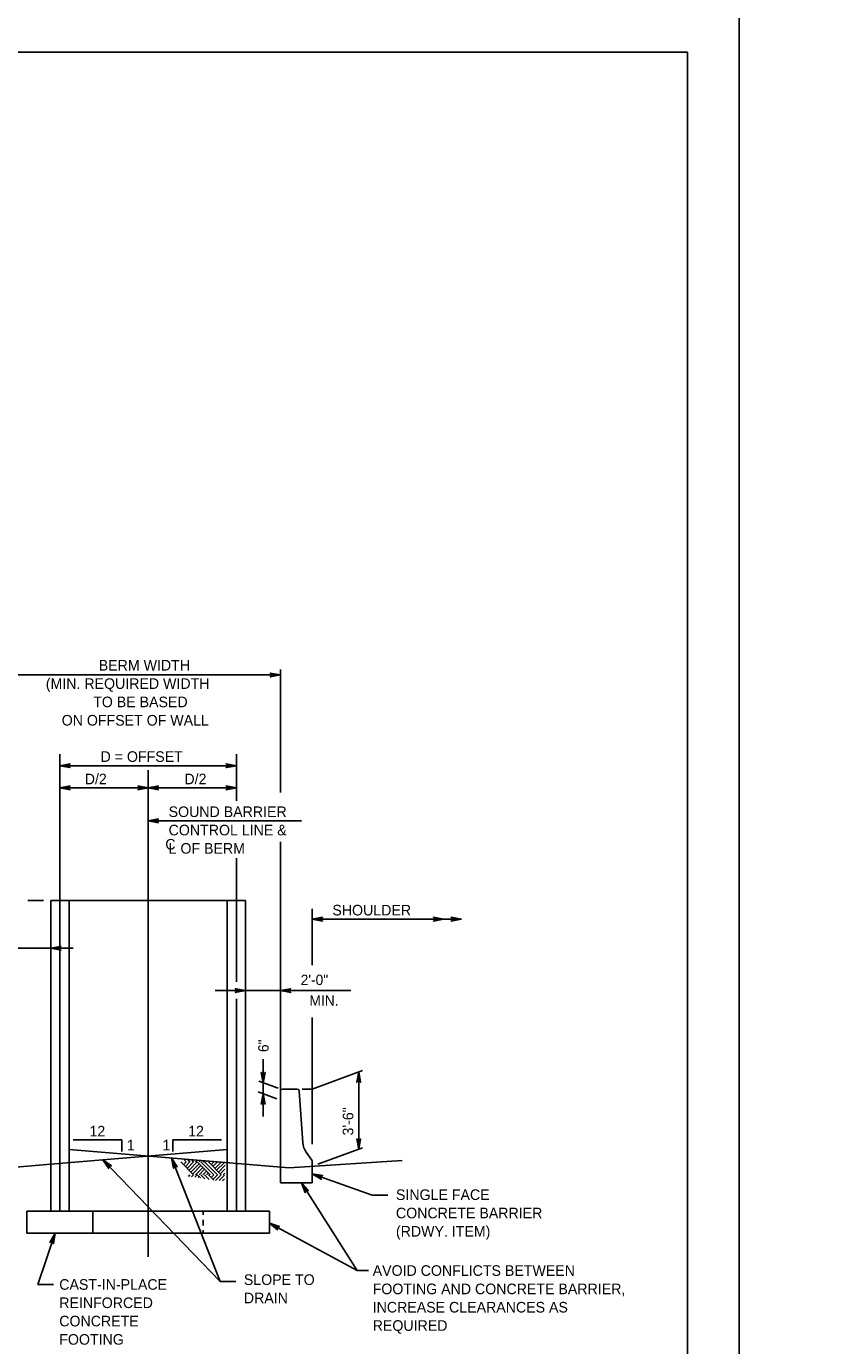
# Model space of a CAD drawing. Extents: x 3385 to 6532, y -616 to 1166.
# Drawn here: x 4395.6 to 4629.5, y 181.7 to 564.2 of the extents above; entities that cross this region are included whole.
import ezdxf

# ---------------------------------------------------------------- set-up
doc = ezdxf.new("R2010")
doc.units = 0
for name, color, linetype in [('1', 7, 'Continuous'), ('2', 7, 'Continuous'), ('PLT-BNDY', 7, 'Continuous')]:
    doc.layers.add(name, color=color, linetype=linetype)

msp = doc.modelspace()

# ---------------------------------------------------------------- linework, layer by layer
at = {"layer": '1'}
for p, q in [((4392.54, 376.13), (4469.34, 376.13)), ((4469.34, 377.67), (4469.34, 342.04)), ((4405.34, 353.19), (4405.34, 220.62)), ((4456.54, 353.19), (4456.54, 339.58)), ((4405.34, 349.81), (4456.54, 349.81)), ((4430.94, 348.49), (4430.94, 207.41)), ((4405.34, 343.41), (4456.54, 343.41)), ((4430.94, 333.81), (4475.42, 333.81)), ((4469.34, 327.78), (4469.34, 253.06)), ((4456.54, 323.03), (4456.54, 287.16)), ((4396.01, 310.76), (4400.62, 310.76)), ((4402.68, 310.76), (4402.68, 220.62)), ((4402.68, 310.76), (4459.21, 310.76)), ((4408.01, 310.76), (4408.01, 220.62)), ((4453.88, 310.76), (4453.88, 220.62)), ((4459.21, 310.76), (4459.21, 220.62)), ((4478.55, 308.31), (4478.55, 291.94)), ((4478.55, 305.32), (4521.77, 305.32)), ((4373.95, 296.86), (4409.23, 296.86)), ((4450.39, 284.59), (4489.76, 284.59)), ((4456.54, 282.2), (4456.54, 220.62)), ((4478.55, 276.76), (4478.55, 240.11)), ((4464.31, 264.69), (4464.31, 248.13)), ((4478.55, 256.04), (4493.11, 261.41)), ((4492.02, 261.01), (4492.02, 238.61)), ((4468.63, 256.31), (4463.09, 258.35)), ((4468.27, 253.24), (4462.81, 255.25)), ((4469.34, 255.51), (4469.34, 228.84)), ((4469.88, 256.04), (4474.18, 256.04)), ((4474.71, 255.55), (4475.77, 240.48)), ((4475.65, 256.04), (4478.55, 256.04)), ((4409.21, 241.35), (4423.31, 241.35)), ((4423.31, 241.35), (4423.31, 237.93)), ((4452.19, 241.35), (4438.09, 241.35)), ((4438.09, 241.35), (4438.09, 237.93)), ((4402.68, 234.27), (4453.88, 238.54)), ((4471.83, 233.22), (4408.01, 238.54)), ((4476.75, 237.75), (4478.45, 235.38)), ((4480.13, 234.23), (4493.15, 239.02)), ((4392.54, 233.42), (4402.68, 234.27)), ((4451.8, 200.27), (4417.85, 235.53)), ((4451.8, 200.27), (4437.74, 236.06)), ((4444.14, 231.19), (4440.41, 234.92)), ((4442.01, 234.92), (4441.16, 235.77)), ((4441.21, 234.12), (4442.01, 234.92)), ((4441.74, 233.59), (4443.07, 234.92)), ((4442.27, 233.05), (4444.14, 234.92)), ((4443.07, 234.92), (4442.32, 235.68)), ((4442.81, 232.52), (4445.21, 234.92)), ((4443.34, 231.99), (4445.74, 234.39)), ((4444.14, 234.92), (4443.48, 235.58)), ((4443.87, 235.19), (4444.21, 235.52)), ((4443.87, 231.45), (4446.27, 233.85)), ((4444.67, 234.92), (4445.19, 235.44)), ((4448.94, 231.19), (4445.21, 234.92)), ((4445.74, 234.92), (4446.18, 235.36)), ((4450.01, 231.19), (4446.27, 234.92)), ((4446.81, 234.92), (4447.16, 235.27)), ((4451.08, 231.19), (4447.34, 234.92)), ((4447.88, 234.92), (4448.15, 235.19)), ((4452.14, 231.19), (4448.41, 234.92)), ((4448.94, 234.92), (4448.72, 235.14)), ((4449.21, 234.12), (4450.01, 234.92)), ((4449.74, 233.59), (4451.08, 234.92)), ((4450.01, 234.92), (4449.88, 235.05)), ((4450.28, 233.05), (4452.08, 234.86)), ((4450.81, 232.52), (4453.07, 234.78)), ((4451.08, 234.92), (4451.05, 234.95)), ((4451.34, 231.99), (4453.21, 233.85)), ((4453.21, 233.85), (4453.26, 233.91)), ((4471.83, 233.22), (4504.63, 235.29)), ((4478.55, 235.07), (4478.55, 228.84)), ((4442.61, 230.72), (4443.07, 231.19)), ((4443.56, 230.6), (4444.14, 231.19)), ((4444.5, 230.48), (4445.21, 231.19)), ((4444.67, 231.19), (4446.81, 233.32)), ((4446.12, 230.28), (4445.21, 231.19)), ((4445.45, 230.36), (4445.74, 230.65)), ((4445.74, 231.19), (4447.34, 232.79)), ((4447.4, 230.06), (4446.27, 231.19)), ((4446.81, 231.19), (4447.88, 232.25)), ((4448.69, 229.84), (4447.34, 231.19)), ((4447.88, 231.19), (4448.41, 231.72)), ((4449.98, 229.62), (4448.41, 231.19)), ((4449.21, 230.39), (4450.01, 231.19)), ((4449.74, 229.85), (4451.08, 231.19)), ((4450.5, 229.54), (4452.14, 231.19)), ((4451.51, 229.49), (4453.12, 231.1)), ((4451.88, 231.45), (4453.21, 232.78)), ((4452.52, 229.44), (4453.06, 229.98)), ((4452.68, 231.19), (4453.15, 231.66)), ((4478.55, 231.43), (4495.91, 225.31)), ((4469.34, 228.84), (4478.55, 228.84)), ((4495.91, 225.31), (4500.46, 225.31)), ((4395.74, 220.62), (4466.14, 220.62)), ((4395.74, 220.62), (4395.74, 214.22)), ((4414.94, 220.62), (4414.94, 214.22)), ((4446.94, 220.62), (4446.94, 219.58)), ((4446.94, 218.11), (4446.94, 216.47)), ((4466.14, 220.62), (4466.14, 214.22)), ((4395.74, 214.22), (4466.14, 214.22)), ((4398.95, 199.36), (4403.97, 214.22)), ((4446.94, 215.09), (4446.94, 214.22)), ((4398.95, 199.36), (4403.49, 199.36)), ((4451.8, 200.27), (4456.34, 200.27))]:
    msp.add_line(p, q, dxfattribs=at)
for points in [[(4469.34, 376.13), (4466.36, 375.57), (4466.59, 375.73), (4466.71, 375.93), (4466.74, 376.13), (4466.71, 376.33), (4466.59, 376.53), (4466.36, 376.69), (4469.34, 376.13), (4466.59, 376.53), (4466.71, 376.33), (4469.34, 376.13), (4466.74, 376.13), (4466.71, 375.93), (4469.34, 376.13), (4466.59, 375.73)], [(4405.34, 349.81), (4408.33, 350.37), (4408.21, 350.29), (4408.1, 350.21), (4408.04, 350.11), (4407.98, 350.01), (4407.96, 349.91), (4407.94, 349.81), (4407.96, 349.71), (4407.98, 349.61), (4408.04, 349.51), (4408.1, 349.41), (4408.21, 349.33), (4408.33, 349.25), (4405.34, 349.81), (4408.21, 349.33), (4408.1, 349.41), (4405.34, 349.81), (4408.04, 349.51), (4407.98, 349.61), (4405.34, 349.81), (4407.96, 349.71), (4407.94, 349.81), (4405.34, 349.81), (4407.96, 349.91), (4407.98, 350.01), (4405.34, 349.81), (4408.04, 350.11), (4408.1, 350.21), (4405.34, 349.81), (4408.21, 350.29)], [(4456.54, 349.81), (4453.56, 349.25), (4453.68, 349.33), (4453.79, 349.41), (4453.85, 349.51), (4453.91, 349.61), (4453.93, 349.71), (4453.94, 349.81), (4453.93, 349.91), (4453.91, 350.01), (4453.85, 350.11), (4453.79, 350.21), (4453.68, 350.29), (4453.56, 350.37), (4456.54, 349.81), (4453.68, 350.29), (4453.79, 350.21), (4456.54, 349.81), (4453.85, 350.11), (4453.91, 350.01), (4456.54, 349.81), (4453.93, 349.91), (4453.94, 349.81), (4456.54, 349.81), (4453.93, 349.71), (4453.91, 349.61), (4456.54, 349.81), (4453.85, 349.51), (4453.79, 349.41), (4456.54, 349.81), (4453.68, 349.33)], [(4405.34, 343.41), (4408.33, 343.97), (4408.21, 343.89), (4408.1, 343.81), (4408.04, 343.71), (4407.98, 343.61), (4407.96, 343.51), (4407.94, 343.41), (4407.96, 343.31), (4407.98, 343.21), (4408.04, 343.11), (4408.1, 343.01), (4408.21, 342.93), (4408.33, 342.85), (4405.34, 343.41), (4408.21, 342.93), (4408.1, 343.01), (4405.34, 343.41), (4408.04, 343.11), (4407.98, 343.21), (4405.34, 343.41), (4407.96, 343.31), (4407.94, 343.41), (4405.34, 343.41), (4407.96, 343.51), (4407.98, 343.61), (4405.34, 343.41), (4408.04, 343.71), (4408.1, 343.81), (4405.34, 343.41), (4408.21, 343.89)], [(4430.94, 343.41), (4427.96, 342.85), (4428.08, 342.93), (4428.19, 343.01), (4428.25, 343.11), (4428.31, 343.21), (4428.33, 343.31), (4428.34, 343.41), (4428.33, 343.51), (4428.31, 343.61), (4428.25, 343.71), (4428.19, 343.81), (4428.08, 343.89), (4427.96, 343.97), (4430.94, 343.41), (4428.08, 343.89), (4428.19, 343.81), (4430.94, 343.41), (4428.25, 343.71), (4428.31, 343.61), (4430.94, 343.41), (4428.33, 343.51), (4428.34, 343.41), (4430.94, 343.41), (4428.33, 343.31), (4428.31, 343.21), (4430.94, 343.41), (4428.25, 343.11), (4428.19, 343.01), (4430.94, 343.41), (4428.08, 342.93)], [(4430.94, 343.41), (4433.93, 342.85), (4433.81, 342.93), (4433.7, 343.01), (4433.64, 343.11), (4433.58, 343.21), (4433.56, 343.31), (4433.54, 343.41), (4433.56, 343.51), (4433.58, 343.61), (4433.64, 343.71), (4433.7, 343.81), (4433.81, 343.89), (4433.93, 343.97), (4430.94, 343.41), (4433.81, 343.89), (4433.7, 343.81), (4430.94, 343.41), (4433.64, 343.71), (4433.58, 343.61), (4430.94, 343.41), (4433.56, 343.51), (4433.54, 343.41), (4430.94, 343.41), (4433.56, 343.31), (4433.58, 343.21), (4430.94, 343.41), (4433.64, 343.11), (4433.7, 343.01), (4430.94, 343.41), (4433.81, 342.93)], [(4456.54, 343.41), (4453.56, 342.85), (4453.68, 342.93), (4453.79, 343.01), (4453.85, 343.11), (4453.91, 343.21), (4453.93, 343.31), (4453.94, 343.41), (4453.93, 343.51), (4453.91, 343.61), (4453.85, 343.71), (4453.79, 343.81), (4453.68, 343.89), (4453.56, 343.97), (4456.54, 343.41), (4453.68, 343.89), (4453.79, 343.81), (4456.54, 343.41), (4453.85, 343.71), (4453.91, 343.61), (4456.54, 343.41), (4453.93, 343.51), (4453.94, 343.41), (4456.54, 343.41), (4453.93, 343.31), (4453.91, 343.21), (4456.54, 343.41), (4453.85, 343.11), (4453.79, 343.01), (4456.54, 343.41), (4453.68, 342.93)], [(4430.94, 333.81), (4433.93, 334.37), (4433.81, 334.29), (4433.7, 334.21), (4433.64, 334.11), (4433.58, 334.01), (4433.56, 333.91), (4433.54, 333.81), (4433.56, 333.71), (4433.58, 333.61), (4433.64, 333.51), (4433.7, 333.41), (4433.81, 333.33), (4433.93, 333.25), (4430.94, 333.81), (4433.81, 333.33), (4433.7, 333.41), (4430.94, 333.81), (4433.64, 333.51), (4433.58, 333.61), (4430.94, 333.81), (4433.56, 333.71), (4433.54, 333.81), (4430.94, 333.81), (4433.56, 333.91), (4433.58, 334.01), (4430.94, 333.81), (4433.64, 334.11), (4433.7, 334.21), (4430.94, 333.81), (4433.81, 334.29)], [(4478.55, 305.32), (4481.53, 305.88), (4481.3, 305.72), (4481.18, 305.52), (4481.15, 305.32), (4481.18, 305.12), (4481.3, 304.92), (4481.53, 304.76), (4478.55, 305.32), (4481.3, 304.92), (4481.18, 305.12), (4478.55, 305.32), (4481.15, 305.32), (4481.18, 305.52), (4478.55, 305.32), (4481.3, 305.72)], [(4516.65, 305.32), (4513.67, 304.76), (4513.78, 304.84), (4513.9, 304.92), (4513.96, 305.02), (4514.02, 305.12), (4514.03, 305.22), (4514.05, 305.32), (4514.03, 305.42), (4514.02, 305.52), (4513.96, 305.62), (4513.9, 305.72), (4513.78, 305.8), (4513.67, 305.88), (4516.65, 305.32), (4513.78, 305.8), (4513.9, 305.72), (4516.65, 305.32), (4513.96, 305.62), (4514.02, 305.52), (4516.65, 305.32), (4514.03, 305.42), (4514.05, 305.32), (4516.65, 305.32), (4514.03, 305.22), (4514.02, 305.12), (4516.65, 305.32), (4513.96, 305.02), (4513.9, 304.92), (4516.65, 305.32), (4513.78, 304.84)], [(4521.77, 305.32), (4518.79, 304.76), (4518.9, 304.84), (4519.02, 304.92), (4519.08, 305.02), (4519.14, 305.12), (4519.15, 305.22), (4519.17, 305.32), (4519.15, 305.42), (4519.14, 305.52), (4519.08, 305.62), (4519.02, 305.72), (4518.9, 305.8), (4518.79, 305.88), (4521.77, 305.32), (4518.9, 305.8), (4519.02, 305.72), (4521.77, 305.32), (4519.08, 305.62), (4519.14, 305.52), (4521.77, 305.32), (4519.15, 305.42), (4519.17, 305.32), (4521.77, 305.32), (4519.15, 305.22), (4519.14, 305.12), (4521.77, 305.32), (4519.08, 305.02), (4519.02, 304.92), (4521.77, 305.32), (4518.9, 304.84)], [(4402.68, 296.86), (4405.66, 297.42), (4405.54, 297.34), (4405.43, 297.26), (4405.37, 297.16), (4405.31, 297.06), (4405.29, 296.96), (4405.28, 296.86), (4405.29, 296.76), (4405.31, 296.66), (4405.37, 296.56), (4405.43, 296.46), (4405.54, 296.38), (4405.66, 296.3), (4402.68, 296.86), (4405.54, 296.38), (4405.43, 296.46), (4402.68, 296.86), (4405.37, 296.56), (4405.31, 296.66), (4402.68, 296.86), (4405.29, 296.76), (4405.28, 296.86), (4402.68, 296.86), (4405.29, 296.96), (4405.31, 297.06), (4402.68, 296.86), (4405.37, 297.16), (4405.43, 297.26), (4402.68, 296.86), (4405.54, 297.34)], [(4459.21, 284.59), (4456.23, 284.03), (4456.34, 284.11), (4456.46, 284.19), (4456.52, 284.29), (4456.58, 284.39), (4456.59, 284.49), (4456.61, 284.59), (4456.59, 284.69), (4456.58, 284.79), (4456.52, 284.89), (4456.46, 284.99), (4456.34, 285.07), (4456.23, 285.15), (4459.21, 284.59), (4456.34, 285.07), (4456.46, 284.99), (4459.21, 284.59), (4456.52, 284.89), (4456.58, 284.79), (4459.21, 284.59), (4456.59, 284.69), (4456.61, 284.59), (4459.21, 284.59), (4456.59, 284.49), (4456.58, 284.39), (4459.21, 284.59), (4456.52, 284.29), (4456.46, 284.19), (4459.21, 284.59), (4456.34, 284.11)], [(4469.34, 284.59), (4472.33, 285.15), (4472.21, 285.07), (4472.1, 284.99), (4472.04, 284.89), (4471.98, 284.79), (4471.96, 284.69), (4471.94, 284.59), (4471.96, 284.49), (4471.98, 284.39), (4472.04, 284.29), (4472.1, 284.19), (4472.21, 284.11), (4472.33, 284.03), (4469.34, 284.59), (4472.21, 284.11), (4472.1, 284.19), (4469.34, 284.59), (4472.04, 284.29), (4471.98, 284.39), (4469.34, 284.59), (4471.96, 284.49), (4471.94, 284.59), (4469.34, 284.59), (4471.96, 284.69), (4471.98, 284.79), (4469.34, 284.59), (4472.04, 284.89), (4472.1, 284.99), (4469.34, 284.59), (4472.21, 285.07)], [(4464.31, 257.89), (4463.75, 260.88), (4463.91, 260.65), (4464.11, 260.53), (4464.31, 260.49), (4464.51, 260.53), (4464.71, 260.65), (4464.87, 260.88), (4464.31, 257.89), (4464.71, 260.65), (4464.51, 260.53), (4464.31, 257.89), (4464.31, 260.49), (4464.11, 260.53), (4464.31, 257.89), (4463.91, 260.65)], [(4492.02, 261.01), (4492.58, 258.02), (4492.5, 258.14), (4492.42, 258.25), (4492.32, 258.31), (4492.22, 258.37), (4492.12, 258.39), (4492.02, 258.41), (4491.92, 258.39), (4491.82, 258.37), (4491.72, 258.31), (4491.62, 258.25), (4491.54, 258.14), (4491.47, 258.02), (4492.02, 261.01), (4491.54, 258.14), (4491.62, 258.25), (4492.02, 261.01), (4491.72, 258.31), (4491.82, 258.37), (4492.02, 261.01), (4491.92, 258.39), (4492.02, 258.41), (4492.02, 261.01), (4492.12, 258.39), (4492.22, 258.37), (4492.02, 261.01), (4492.32, 258.31), (4492.42, 258.25), (4492.02, 261.01), (4492.5, 258.14)], [(4464.31, 254.69), (4464.87, 251.71), (4464.71, 251.94), (4464.51, 252.06), (4464.31, 252.09), (4464.11, 252.06), (4463.91, 251.94), (4463.75, 251.71), (4464.31, 254.69), (4463.91, 251.94), (4464.11, 252.06), (4464.31, 254.69), (4464.31, 252.09), (4464.51, 252.06), (4464.31, 254.69), (4464.71, 251.94)], [(4492.02, 238.61), (4491.47, 241.59), (4491.54, 241.47), (4491.62, 241.36), (4491.72, 241.3), (4491.82, 241.24), (4491.92, 241.22), (4492.02, 241.21), (4492.12, 241.22), (4492.22, 241.24), (4492.32, 241.3), (4492.42, 241.36), (4492.5, 241.47), (4492.58, 241.59), (4492.02, 238.61), (4492.5, 241.47), (4492.42, 241.36), (4492.02, 238.61), (4492.32, 241.3), (4492.22, 241.24), (4492.02, 238.61), (4492.12, 241.22), (4492.02, 241.21), (4492.02, 238.61), (4491.92, 241.22), (4491.82, 241.24), (4492.02, 238.61), (4491.72, 241.3), (4491.62, 241.36), (4492.02, 238.61), (4491.54, 241.47)], [(4417.85, 235.53), (4420.32, 233.77), (4420.04, 233.83), (4419.82, 233.77), (4419.65, 233.66), (4419.53, 233.5), (4419.47, 233.27), (4419.51, 233), (4417.85, 235.53), (4419.47, 233.27), (4419.53, 233.5), (4417.85, 235.53), (4419.65, 233.66), (4419.82, 233.77), (4417.85, 235.53), (4420.04, 233.83)], [(4437.74, 236.06), (4439.35, 233.49), (4439.12, 233.64), (4438.89, 233.68), (4438.69, 233.64), (4438.52, 233.53), (4438.37, 233.35), (4438.31, 233.08), (4437.74, 236.06), (4438.37, 233.35), (4438.52, 233.53), (4437.74, 236.06), (4438.69, 233.64), (4438.89, 233.68), (4437.74, 236.06), (4439.12, 233.64)], [(4478.55, 231.43), (4481.54, 230.96), (4481.27, 230.89), (4481.1, 230.74), (4481, 230.56), (4480.96, 230.36), (4481.01, 230.13), (4481.17, 229.91), (4478.55, 231.43), (4481.01, 230.13), (4480.96, 230.36), (4478.55, 231.43), (4481, 230.56), (4481.1, 230.74), (4478.55, 231.43), (4481.27, 230.89)], [(4475.38, 228.84), (4491.58, 203.42), (4494.83, 203.42)], [(4475.38, 228.84), (4477.45, 226.63), (4477.32, 226.68), (4477.2, 226.74), (4477.08, 226.73), (4476.96, 226.73), (4476.87, 226.69), (4476.78, 226.65), (4476.7, 226.58), (4476.63, 226.51), (4476.57, 226.41), (4476.52, 226.31), (4476.52, 226.17), (4476.51, 226.03), (4475.38, 228.84), (4476.52, 226.17), (4476.52, 226.31), (4475.38, 228.84), (4476.57, 226.41), (4476.63, 226.51), (4475.38, 228.84), (4476.7, 226.58), (4476.78, 226.65), (4475.38, 228.84), (4476.87, 226.69), (4476.96, 226.73), (4475.38, 228.84), (4477.08, 226.73), (4477.2, 226.74), (4475.38, 228.84), (4477.32, 226.68)], [(4403.97, 214.22), (4403.54, 211.22), (4403.47, 211.49), (4403.31, 211.66), (4403.14, 211.76), (4402.93, 211.79), (4402.71, 211.74), (4402.48, 211.58), (4403.97, 214.22), (4402.71, 211.74), (4402.93, 211.79), (4403.97, 214.22), (4403.14, 211.76), (4403.31, 211.66), (4403.97, 214.22), (4403.47, 211.49)], [(4466.14, 217.15), (4491.58, 203.42)], [(4466.14, 217.15), (4469.03, 216.22), (4468.9, 216.21), (4468.76, 216.19), (4468.66, 216.13), (4468.56, 216.07), (4468.49, 215.99), (4468.43, 215.91), (4468.4, 215.82), (4468.37, 215.72), (4468.37, 215.61), (4468.38, 215.49), (4468.44, 215.37), (4468.5, 215.24), (4466.14, 217.15), (4468.44, 215.37), (4468.38, 215.49), (4466.14, 217.15), (4468.37, 215.61), (4468.37, 215.72), (4466.14, 217.15), (4468.4, 215.82), (4468.43, 215.91), (4466.14, 217.15), (4468.49, 215.99), (4468.56, 216.07), (4466.14, 217.15), (4468.66, 216.13), (4468.76, 216.19), (4466.14, 217.15), (4468.9, 216.21)]]:
    msp.add_lwpolyline(points, dxfattribs=at)
for centre, radius, start, end in [((4469.88, 255.51), 0.533, 90, 180), ((4474.18, 255.51), 0.533, 4.0219, 90), ((4481.09, 240.85), 5.33, 184.0219, 215.5414), ((4478.01, 235.07), 0.533, 0, 35.5414)]:
    msp.add_arc(centre, radius, start, end, dxfattribs=at)
at = {"layer": '2'}
for p, q in [((3801.34, 556.69), (4587.34, 556.69)), ((4587.34, 556.69), (4587.34, -7.31))]:
    msp.add_line(p, q, dxfattribs=at)
at = {"layer": 'PLT-BNDY'}
for points in [[(3761.34, 571.69), (4602.34, 571.69), (4602.34, -22.31), (3761.34, -22.31)], [(4602.34, 571.69), (5443.34, 571.69), (5443.34, -22.31), (4602.34, -22.31)]]:
    msp.add_lwpolyline(points, close=True, dxfattribs=at)

# ---------------------------------------------------------------- texts
at = {"layer": '1'}
for s, height, p in [('BERM WIDTH', 3.072, (4416.63, 377.39)), ('(MIN. REQUIRED WIDTH', 3.0721, (4401.27, 372.08)), ('TO BE BASED', 3.0721, (4415.01, 366.77)), ('ON OFFSET OF WALL', 3.0721, (4405.88, 361.45)), ('D = OFFSET', 3.072, (4417.15, 350.92)), ('D/2', 3.072, (4412.55, 344.42)), ('D/2', 3.072, (4441.46, 344.42)), ('SOUND BARRIER', 3.0721, (4436.89, 334.93)), ('CONTROL LINE &', 3.0721, (4436.89, 329.61)), ('C', 3.07, (4435.93, 325.49)), ('L OF BERM', 3.072, (4436.89, 324.3)), ('SHOULDER', 3.072, (4484.38, 306.39)), ('2\'-0"', 3, (4475.18, 286.21)), ('MIN.', 3, (4477.72, 280.21)), ('12', 3.072, (4413.93, 242.31)), ('12', 3.072, (4442.55, 242.31)), ('1', 3.07, (4424.75, 238.26)), ('1', 3.07, (4435.08, 238.26)), ('SINGLE FACE', 3.0721, (4502.82, 223.88)), ('CONCRETE BARRIER', 3.0721, (4502.82, 218.57)), ('(RDWY. ITEM)', 3.0721, (4502.82, 213.26)), ('AVOID CONFLICTS BETWEEN', 3.0721, (4496.07, 201.88)), ('CAST-IN-PLACE', 3.0721, (4405.17, 197.85)), ('SLOPE TO', 3.072, (4458.71, 199.24)), ('FOOTING AND CONCRETE BARRIER,', 3.0721, (4496.07, 196.56)), ('REINFORCED', 3.072, (4405.17, 192.54)), ('DRAIN', 3.072, (4458.71, 193.93)), ('INCREASE CLEARANCES AS', 3.0721, (4496.07, 191.25)), ('CONCRETE', 3.072, (4405.17, 187.23)), ('REQUIRED', 3.072, (4496.07, 185.94)), ('FOOTING', 3.072, (4405.17, 181.92))]:
    msp.add_text(s, height=height, dxfattribs=at).set_placement(p)
for s, height, p in [('6"', 3, (4465.88, 266.77)), ('3\'-6"', 3.072, (4490.45, 242.58))]:
    msp.add_text(s, height=height, rotation=90, dxfattribs=at).set_placement(p)

doc.saveas('drawing.dxf')
